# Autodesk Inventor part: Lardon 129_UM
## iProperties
Created: 2011-12
Part Number: Lardon 129_UM
Document SubType Name: Modeling
Designer: A
Manufacturer: Standard
Standards Organization: Custom
Author: A
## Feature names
1. Extrusion1
2. Perçage1 [Hole]
3. Chanfrein1 [Chamfer]
